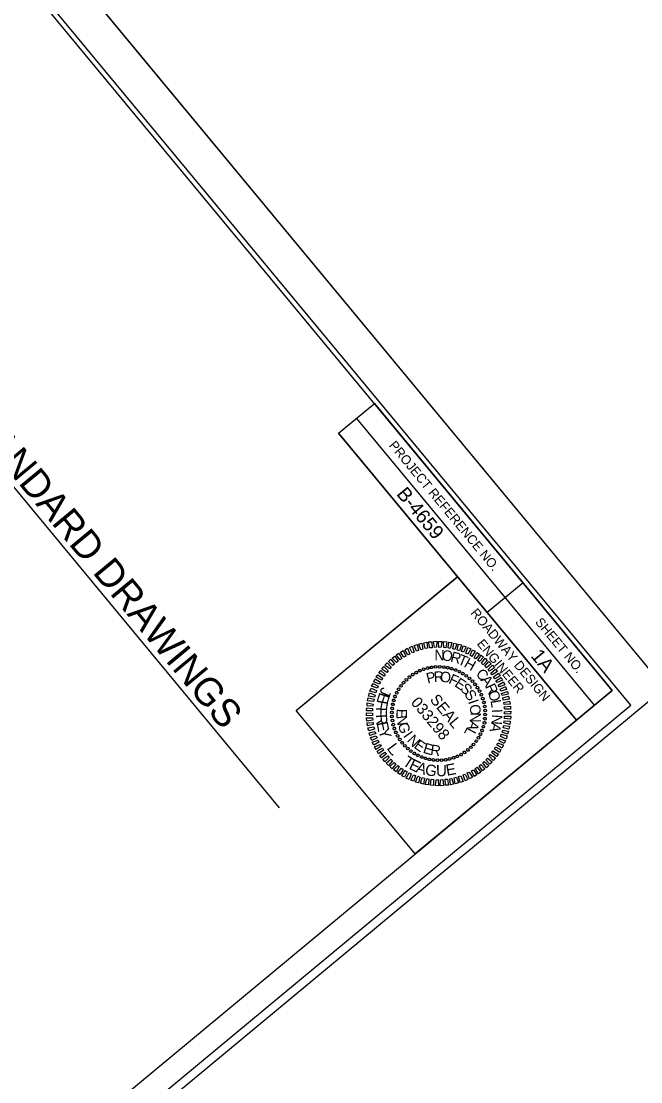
# Model space of a CAD drawing. Extents: x 2054826 to 2060231, y 685508 to 690809.
# Drawn here: x 2056398 to 2056731, y 685996 to 686565 of the extents above; entities that cross this region are included whole.
import ezdxf

# ---------------------------------------------------------------- set-up
doc = ezdxf.new("R2010")
doc.units = 0
for name, color, linetype in [('Prop DSN Text', 7, 'Continuous'), ('Sheet Cutting Line CELL', 7, 'Continuous'), ('Sheet Data Field CELL', 7, 'Continuous'), ('Sheet Plan CELL', 7, 'Continuous'), ('Sheet Plot Border Inside CELL', 7, 'Continuous'), ('Sheet Plot Border Outside CELL', 7, 'Continuous'), ('Sheet Professional Seal CELL', 7, 'Continuous')]:
    doc.layers.add(name, color=color, linetype=linetype)

msp = doc.modelspace()

# ---------------------------------------------------------------- linework, layer by layer
at = {"layer": 'Prop DSN Text'}
msp.add_line((2056196.26, 686553.18), (2056536.33, 686143.09), dxfattribs=at)
at = {"layer": 'Sheet Cutting Line CELL'}
msp.add_line((2056743.36, 686207.34), (2055668.74, 687503.24), dxfattribs=at)
at = {"layer": 'Sheet Plan CELL'}
for p, q in [((2056577.83, 686352.04), (2056705.53, 686198.05)), ((2056568.21, 686344.06), (2056695.91, 686190.07)), ((2056568.21, 686344.06), (2056695.91, 686190.07)), ((2056632.08, 686267.05), (2056545.52, 686195.27)), ((2056667.28, 686263.76), (2056648.03, 686247.81))]:
    msp.add_line(p, q, dxfattribs=at)
for points in [[(2056715.19, 686206.06), (2055757.7, 687360.71), (2054949.45, 686690.47), (2055906.94, 685535.82)], [(2056587.49, 686360.05), (2056715.19, 686206.06), (2056695.91, 686190.07), (2056568.21, 686344.06)], [(2056632.08, 686267.05), (2056695.91, 686190.07), (2056609.31, 686118.26), (2056545.48, 686195.24)]]:
    msp.add_lwpolyline(points, close=True, dxfattribs=at)
at = {"layer": 'Sheet Plot Border Inside CELL'}
msp.add_lwpolyline([(2054849.54, 686807.03), (2055912.99, 685524.6), (2056725.1, 686198.04), (2055661.64, 687480.47)], close=True, dxfattribs=at)
at = {"layer": 'Sheet Plot Border Outside CELL'}
msp.add_lwpolyline([(2054825.85, 686804.27), (2055900.47, 685508.37), (2056743.36, 686207.34), (2055668.74, 687503.24)], close=True, dxfattribs=at)
at = {"layer": 'Sheet Professional Seal CELL'}
for p, q in [((2056622.51, 686218.76), (2056622.51, 686218.76)), ((2056606.23, 686213.25), (2056606.23, 686213.25)), ((2056608.02, 686214.54), (2056608.02, 686214.54)), ((2056609.9, 686215.64), (2056609.9, 686215.64)), ((2056611.8, 686216.63), (2056611.8, 686216.63)), ((2056613.86, 686217.44), (2056613.86, 686217.44)), ((2056615.98, 686218.02), (2056615.98, 686218.02)), ((2056618.12, 686218.49), (2056618.12, 686218.49)), ((2056620.3, 686218.68), (2056620.3, 686218.68)), ((2056624.66, 686218.59), (2056624.66, 686218.59)), ((2056626.87, 686218.28), (2056626.87, 686218.28)), ((2056628.95, 686217.73), (2056628.95, 686217.73)), ((2056631.05, 686217), (2056631.05, 686217)), ((2056633.06, 686216.14), (2056633.06, 686216.14)), ((2056634.95, 686215.11), (2056634.95, 686215.11)), ((2056636.76, 686213.88), (2056636.76, 686213.88)), ((2056601.67, 686208.49), (2056601.67, 686208.49)), ((2056603.1, 686210.2), (2056603.1, 686210.2)), ((2056604.57, 686211.8), (2056604.57, 686211.8)), ((2056638.47, 686212.44), (2056638.47, 686212.44)), ((2056640.07, 686210.98), (2056640.07, 686210.98)), ((2056641.51, 686209.31), (2056641.51, 686209.31)), ((2056642.8, 686207.53), (2056642.8, 686207.53)), ((2056598.54, 686202.78), (2056598.54, 686202.78)), ((2056599.4, 686204.79), (2056599.4, 686204.79)), ((2056600.43, 686206.69), (2056600.43, 686206.69)), ((2056643.91, 686205.65), (2056643.91, 686205.65)), ((2056644.9, 686203.74), (2056644.9, 686203.74)), ((2056645.7, 686201.68), (2056645.7, 686201.68)), ((2056596.95, 686196.39), (2056596.95, 686196.39)), ((2056597.26, 686198.6), (2056597.26, 686198.6)), ((2056597.81, 686200.68), (2056597.81, 686200.68)), ((2056646.29, 686199.57), (2056646.29, 686199.57)), ((2056646.76, 686197.43), (2056646.76, 686197.43)), ((2056596.79, 686194.24), (2056596.79, 686194.24)), ((2056596.86, 686192.04), (2056596.86, 686192.04)), ((2056621.91, 686193.64), (2056621.91, 686193.64)), ((2056646.86, 686190.88), (2056646.86, 686190.88)), ((2056646.95, 686195.24), (2056646.95, 686195.24)), ((2056647.03, 686193.03), (2056647.03, 686193.03)), ((2056597.05, 686189.85), (2056597.05, 686189.85)), ((2056597.53, 686187.71), (2056597.53, 686187.71)), ((2056598.11, 686185.6), (2056598.11, 686185.6)), ((2056646, 686186.6), (2056646, 686186.6)), ((2056646.55, 686188.68), (2056646.55, 686188.68)), ((2056598.91, 686183.53), (2056598.91, 686183.53)), ((2056599.91, 686181.63), (2056599.91, 686181.63)), ((2056601.01, 686179.75), (2056601.01, 686179.75)), ((2056643.38, 686180.59), (2056643.38, 686180.59)), ((2056644.41, 686182.48), (2056644.41, 686182.48)), ((2056645.27, 686184.5), (2056645.27, 686184.5)), ((2056602.3, 686177.96), (2056602.3, 686177.96)), ((2056603.74, 686176.3), (2056603.74, 686176.3)), ((2056605.34, 686174.84), (2056605.34, 686174.84)), ((2056607.06, 686173.4), (2056607.06, 686173.4)), ((2056637.58, 686174.03), (2056637.58, 686174.03)), ((2056639.24, 686175.47), (2056639.24, 686175.47)), ((2056640.71, 686177.08), (2056640.71, 686177.08)), ((2056642.14, 686178.79), (2056642.14, 686178.79)), ((2056608.86, 686172.17), (2056608.86, 686172.17)), ((2056610.75, 686171.14), (2056610.75, 686171.14)), ((2056612.76, 686170.28), (2056612.76, 686170.28)), ((2056614.86, 686169.55), (2056614.86, 686169.55)), ((2056616.94, 686169), (2056616.94, 686169)), ((2056619.15, 686168.68), (2056619.15, 686168.68)), ((2056621.3, 686168.52), (2056621.3, 686168.52)), ((2056623.51, 686168.6), (2056623.51, 686168.6)), ((2056625.69, 686168.78), (2056625.69, 686168.78)), ((2056627.83, 686169.26), (2056627.83, 686169.26)), ((2056629.95, 686169.84), (2056629.95, 686169.84)), ((2056632.01, 686170.64), (2056632.01, 686170.64)), ((2056633.91, 686171.64), (2056633.91, 686171.64)), ((2056635.79, 686172.74), (2056635.79, 686172.74))]:
    msp.add_line(p, q, dxfattribs=at)
for points in [[(2056610.02, 686227.17), (2056608.73, 686230.13), (2056610.34, 686230.62), (2056611.17, 686227.42)], [(2056612.35, 686227.8), (2056611.25, 686230.92), (2056612.93, 686231.34), (2056613.51, 686228.12)], [(2056614.76, 686228.5), (2056613.9, 686231.49), (2056615.57, 686231.91), (2056615.87, 686228.65)], [(2056617.18, 686228.95), (2056616.54, 686232.06), (2056618.26, 686232.19), (2056618.38, 686228.91)], [(2056619.67, 686229.07), (2056619.26, 686232.24), (2056620.98, 686232.43), (2056620.82, 686229.18)], [(2056622.09, 686229.13), (2056621.94, 686232.38), (2056623.64, 686232.36), (2056623.23, 686229.17)], [(2056624.67, 686229), (2056624.62, 686232.27), (2056626.31, 686232.04), (2056625.8, 686228.89)], [(2056627.07, 686228.84), (2056627.36, 686231.94), (2056629.05, 686231.78), (2056628.22, 686228.56)], [(2056629.54, 686228.29), (2056630.02, 686231.48), (2056631.69, 686231.11), (2056630.65, 686227.98)], [(2056631.91, 686227.79), (2056632.69, 686230.84), (2056634.25, 686230.45), (2056633.08, 686227.32)], [(2056599.25, 686220.97), (2056597.05, 686223.37), (2056598.36, 686224.46), (2056600.17, 686221.73)], [(2056601.2, 686222.52), (2056599.2, 686225.09), (2056600.54, 686226.06), (2056602.19, 686223.21)], [(2056603.21, 686223.86), (2056601.4, 686226.52), (2056602.83, 686227.45), (2056604.29, 686224.44)], [(2056605.43, 686225.18), (2056603.76, 686227.82), (2056605.29, 686228.64), (2056606.49, 686225.54)], [(2056607.69, 686226.21), (2056606.21, 686229.02), (2056607.7, 686229.8), (2056608.75, 686226.58)], [(2056634.28, 686226.89), (2056635.17, 686230.04), (2056636.78, 686229.36), (2056635.35, 686226.54)], [(2056636.57, 686226), (2056637.71, 686229.02), (2056639.24, 686228.28), (2056637.62, 686225.44)], [(2056638.79, 686224.98), (2056640.19, 686227.83), (2056641.61, 686227.06), (2056639.82, 686224.21)], [(2056640.97, 686223.61), (2056642.54, 686226.41), (2056643.88, 686225.5), (2056641.91, 686223.02)], [(2056643, 686222.17), (2056644.75, 686224.99), (2056646.11, 686223.91), (2056643.86, 686221.52)], [(2056594.14, 686215.69), (2056591.39, 686217.51), (2056592.51, 686218.82), (2056594.75, 686216.59)], [(2056595.7, 686217.57), (2056593.08, 686219.62), (2056594.3, 686220.82), (2056596.49, 686218.49)], [(2056597.35, 686219.33), (2056594.97, 686221.58), (2056596.21, 686222.74), (2056598.21, 686220.17)], [(2056644.95, 686220.68), (2056646.91, 686223.33), (2056648.07, 686222.16), (2056645.84, 686219.85)], [(2056646.72, 686219.02), (2056648.83, 686221.49), (2056650.07, 686220.31), (2056647.6, 686218.19)], [(2056648.5, 686217.26), (2056650.85, 686219.52), (2056651.86, 686218.22), (2056649.23, 686216.3)], [(2056591.34, 686211.55), (2056588.39, 686213.07), (2056589.23, 686214.48), (2056591.82, 686212.6)], [(2056592.67, 686213.7), (2056589.74, 686215.43), (2056590.82, 686216.71), (2056593.26, 686214.64)], [(2056650, 686215.38), (2056652.5, 686217.45), (2056653.51, 686216.15), (2056650.73, 686214.42)], [(2056651.48, 686213.36), (2056654.11, 686215.28), (2056654.93, 686213.81), (2056652.09, 686212.3)], [(2056589.08, 686207.21), (2056585.95, 686208.25), (2056586.73, 686209.74), (2056589.43, 686208.28)], [(2056590.1, 686209.36), (2056587.06, 686210.67), (2056587.88, 686212.19), (2056590.63, 686210.44)], [(2056652.7, 686211.25), (2056655.45, 686212.95), (2056656.31, 686211.52), (2056653.35, 686210.23)], [(2056653.91, 686208.94), (2056656.73, 686210.63), (2056657.51, 686209.06), (2056654.38, 686207.97)], [(2056654.94, 686206.68), (2056657.8, 686208.08), (2056658.41, 686206.57), (2056655.34, 686205.65)], [(2056586.93, 686200.1), (2056583.73, 686200.43), (2056584.1, 686202.1), (2056587.25, 686201.28)], [(2056587.47, 686202.5), (2056584.29, 686203.04), (2056584.8, 686204.7), (2056587.82, 686203.57)], [(2056588.22, 686204.81), (2056585.07, 686205.64), (2056585.61, 686207.32), (2056588.54, 686205.99)], [(2056655.68, 686204.37), (2056658.84, 686205.5), (2056659.27, 686204.04), (2056656.15, 686203.26)], [(2056656.39, 686202.03), (2056659.46, 686202.95), (2056659.91, 686201.31), (2056656.67, 686200.83)], [(2056586.46, 686195.1), (2056583.15, 686195.02), (2056583.31, 686196.71), (2056586.43, 686196.31)], [(2056586.66, 686197.6), (2056583.48, 686197.76), (2056583.64, 686199.45), (2056586.8, 686198.69)], [(2056656.97, 686199.53), (2056660.03, 686200.31), (2056660.33, 686198.61), (2056657.11, 686198.41)], [(2056657.18, 686197.16), (2056660.53, 686197.67), (2056660.55, 686196), (2056657.42, 686195.93)], [(2056586.48, 686192.65), (2056583.18, 686192.32), (2056583.2, 686194.02), (2056586.41, 686193.83)], [(2056586.64, 686190.11), (2056583.29, 686189.61), (2056583.26, 686191.28), (2056586.4, 686191.34)], [(2056657.33, 686194.63), (2056660.63, 686194.96), (2056660.61, 686193.26), (2056657.4, 686193.45)], [(2056657.35, 686192.18), (2056660.66, 686192.26), (2056660.5, 686190.57), (2056657.38, 686190.97)], [(2056586.84, 686187.75), (2056583.79, 686186.97), (2056583.48, 686188.67), (2056586.7, 686188.87)], [(2056587.42, 686185.25), (2056584.36, 686184.33), (2056583.9, 686185.97), (2056587.15, 686186.44)], [(2056656.34, 686184.78), (2056659.52, 686184.23), (2056659.01, 686182.58), (2056655.99, 686183.71)], [(2056656.88, 686187.18), (2056660.08, 686186.84), (2056659.71, 686185.17), (2056656.56, 686186)], [(2056657.15, 686189.67), (2056660.33, 686189.52), (2056660.17, 686187.83), (2056657.01, 686188.59)], [(2056588.13, 686182.91), (2056584.97, 686181.78), (2056584.54, 686183.24), (2056587.66, 686184.02)], [(2056588.87, 686180.6), (2056586.01, 686179.2), (2056585.4, 686180.71), (2056588.47, 686181.63)], [(2056589.9, 686178.34), (2056587.08, 686176.65), (2056586.31, 686178.21), (2056589.43, 686179.31)], [(2056654.73, 686180.06), (2056657.86, 686179.03), (2056657.08, 686177.54), (2056654.38, 686179)], [(2056655.59, 686182.47), (2056658.75, 686181.64), (2056658.2, 686179.95), (2056655.27, 686181.29)], [(2056591.11, 686176.03), (2056588.36, 686174.33), (2056587.5, 686175.76), (2056590.46, 686177.04)], [(2056592.33, 686173.92), (2056589.7, 686172), (2056588.88, 686173.46), (2056591.72, 686174.97)], [(2056651.14, 686173.58), (2056654.07, 686171.85), (2056652.99, 686170.57), (2056650.55, 686172.64)], [(2056652.48, 686175.73), (2056655.42, 686174.21), (2056654.58, 686172.8), (2056651.99, 686174.67)], [(2056653.71, 686177.92), (2056656.75, 686176.61), (2056655.93, 686175.09), (2056653.18, 686176.84)], [(2056593.81, 686171.9), (2056591.31, 686169.83), (2056590.3, 686171.13), (2056593.09, 686172.86)], [(2056595.31, 686170.02), (2056592.96, 686167.76), (2056591.95, 686169.06), (2056594.58, 686170.98)], [(2056597.09, 686168.26), (2056594.98, 686165.79), (2056593.74, 686166.97), (2056596.21, 686169.09)], [(2056646.46, 686167.95), (2056648.84, 686165.7), (2056647.6, 686164.54), (2056645.6, 686167.1)], [(2056648.11, 686169.71), (2056650.73, 686167.65), (2056649.52, 686166.45), (2056647.32, 686168.79)], [(2056649.67, 686171.59), (2056652.42, 686169.77), (2056651.3, 686168.45), (2056649.06, 686170.69)], [(2056598.86, 686166.6), (2056596.91, 686163.94), (2056595.74, 686165.12), (2056597.98, 686167.43)], [(2056600.81, 686165.11), (2056599.06, 686162.29), (2056597.7, 686163.37), (2056599.95, 686165.75)], [(2056602.85, 686163.67), (2056601.27, 686160.87), (2056599.93, 686161.78), (2056601.91, 686164.26)], [(2056605.03, 686162.3), (2056603.62, 686159.45), (2056602.2, 686160.22), (2056604, 686163.07)], [(2056607.24, 686161.27), (2056606.1, 686158.26), (2056604.58, 686159), (2056606.19, 686161.83)], [(2056638.38, 686162.1), (2056640.06, 686159.45), (2056638.52, 686158.64), (2056637.32, 686161.73)], [(2056640.6, 686163.42), (2056642.41, 686160.76), (2056640.98, 686159.83), (2056639.52, 686162.84)], [(2056642.61, 686164.76), (2056644.61, 686162.19), (2056643.27, 686161.21), (2056641.62, 686164.07)], [(2056644.57, 686166.31), (2056646.76, 686163.91), (2056645.45, 686162.82), (2056643.64, 686165.55)], [(2056609.53, 686160.39), (2056608.64, 686157.24), (2056607.03, 686157.92), (2056608.47, 686160.73)], [(2056611.9, 686159.49), (2056611.12, 686156.44), (2056609.56, 686156.83), (2056610.74, 686159.95)], [(2056614.27, 686158.99), (2056613.79, 686155.8), (2056612.12, 686156.17), (2056613.16, 686159.3)], [(2056616.74, 686158.44), (2056616.45, 686155.34), (2056614.76, 686155.49), (2056615.59, 686158.72)], [(2056619.14, 686158.28), (2056619.19, 686155.01), (2056617.5, 686155.24), (2056618.01, 686158.39)], [(2056621.72, 686158.15), (2056621.88, 686154.9), (2056620.17, 686154.92), (2056620.58, 686158.11)], [(2056624.14, 686158.21), (2056624.55, 686155.04), (2056622.83, 686154.85), (2056622.99, 686158.1)], [(2056626.63, 686158.33), (2056627.27, 686155.22), (2056625.55, 686155.09), (2056625.43, 686158.37)], [(2056629.06, 686158.78), (2056629.91, 686155.78), (2056628.24, 686155.37), (2056627.94, 686158.63)], [(2056631.46, 686159.47), (2056632.56, 686156.35), (2056630.89, 686155.94), (2056630.3, 686159.16)], [(2056633.8, 686160.11), (2056635.08, 686157.15), (2056633.47, 686156.66), (2056632.64, 686159.86)], [(2056636.12, 686161.06), (2056637.6, 686158.26), (2056636.11, 686157.48), (2056635.06, 686160.7)]]:
    msp.add_lwpolyline(points, close=True, dxfattribs=at)
for centre, major_axis in [((2056615.98, 686218.01), (-0.17, 0.7)), ((2056618.13, 686218.43), (-0.109, 0.712)), ((2056620.3, 686218.67), (-0.046, 0.719)), ((2056622.49, 686218.71), (0.017, 0.72)), ((2056624.67, 686218.57), (0.079, 0.716)), ((2056626.83, 686218.23), (0.141, 0.706)), ((2056606.24, 686213.22), (-0.45, 0.562)), ((2056608, 686214.51), (-0.399, 0.599)), ((2056609.87, 686215.64), (-0.345, 0.632)), ((2056611.84, 686216.61), (-0.289, 0.659)), ((2056613.88, 686217.4), (-0.23, 0.682)), ((2056628.96, 686217.71), (0.202, 0.691)), ((2056631.03, 686217), (0.262, 0.671)), ((2056633.03, 686216.12), (0.319, 0.645)), ((2056634.95, 686215.06), (0.374, 0.615)), ((2056636.76, 686213.84), (0.427, 0.58)), ((2056638.47, 686212.47), (0.476, 0.541)), ((2056600.48, 686206.68), (-0.615, 0.374)), ((2056601.7, 686208.5), (-0.58, 0.427)), ((2056603.07, 686210.2), (-0.541, 0.476)), ((2056604.59, 686211.78), (-0.497, 0.521)), ((2056640.05, 686210.96), (0.521, 0.497)), ((2056641.49, 686209.31), (0.562, 0.45)), ((2056642.78, 686207.54), (0.599, 0.399)), ((2056598.54, 686202.76), (-0.671, 0.262)), ((2056599.43, 686204.76), (-0.645, 0.319)), ((2056643.91, 686205.67), (0.632, 0.345)), ((2056644.88, 686203.71), (0.659, 0.289)), ((2056645.67, 686201.67), (0.682, 0.23)), ((2056596.98, 686196.41), (-0.716, 0.079)), ((2056597.31, 686198.57), (-0.706, 0.141)), ((2056597.84, 686200.69), (-0.691, 0.202)), ((2056646.28, 686199.57), (0.7, 0.17)), ((2056646.7, 686197.42), (0.712, 0.109)), ((2056646.93, 686195.24), (0.719, 0.046)), ((2056596.83, 686194.22), (-0.72, 0.017)), ((2056596.88, 686192.04), (-0.719, -0.046)), ((2056597.11, 686189.86), (-0.712, -0.109)), ((2056646.83, 686190.87), (0.716, -0.079)), ((2056646.98, 686193.06), (0.72, -0.017)), ((2056597.54, 686187.71), (-0.7, -0.17)), ((2056598.15, 686185.61), (-0.682, -0.23)), ((2056645.27, 686184.52), (0.671, -0.262)), ((2056645.97, 686186.59), (0.691, -0.202)), ((2056646.5, 686188.71), (0.706, -0.141)), ((2056598.94, 686183.57), (-0.659, -0.289)), ((2056599.9, 686181.61), (-0.632, -0.345)), ((2056601.03, 686179.74), (-0.599, -0.399)), ((2056642.11, 686178.78), (0.58, -0.427)), ((2056643.33, 686180.6), (0.615, -0.374)), ((2056644.38, 686182.51), (0.645, -0.319)), ((2056602.32, 686177.97), (-0.562, -0.45)), ((2056603.76, 686176.32), (-0.521, -0.497)), ((2056605.34, 686174.81), (-0.476, -0.541)), ((2056607.05, 686173.43), (-0.427, -0.58)), ((2056635.81, 686172.77), (0.399, -0.599)), ((2056637.58, 686174.06), (0.45, -0.562)), ((2056639.22, 686175.5), (0.497, -0.521)), ((2056640.74, 686177.08), (0.541, -0.476)), ((2056608.86, 686172.22), (-0.374, -0.615)), ((2056610.78, 686171.16), (-0.319, -0.645)), ((2056612.78, 686170.28), (-0.262, -0.671)), ((2056614.85, 686169.57), (-0.202, -0.691)), ((2056616.98, 686169.05), (-0.141, -0.706)), ((2056619.14, 686168.71), (-0.079, -0.716)), ((2056621.32, 686168.57), (-0.017, -0.72)), ((2056623.51, 686168.61), (0.046, -0.719)), ((2056625.69, 686168.85), (0.109, -0.712)), ((2056627.83, 686169.27), (0.17, -0.7)), ((2056629.93, 686169.88), (0.23, -0.682)), ((2056631.97, 686170.67), (0.289, -0.659)), ((2056633.94, 686171.63), (0.345, -0.632))]:
    msp.add_ellipse(centre, major_axis=major_axis, ratio=0.999708, dxfattribs=at)

# ---------------------------------------------------------------- texts
at = {"layer": 'Prop DSN Text'}
msp.add_text('2012 ROADWAY ENGLISH STANDARD DRAWINGS', height=15, rotation=309.6672, dxfattribs=at).set_placement((2056200.16, 686553.28))
at = {"layer": 'Sheet Data Field CELL'}
for s, p in [('B-4659', (2056598.95, 686311.3)), ('1A', (2056671.07, 686224.41))]:
    msp.add_text(s, height=7.5, rotation=309.6672, dxfattribs=at).set_placement(p)
at = {"layer": 'Sheet Plan CELL'}
for s, height, p in [('PROJECT REFERENCE NO.', 5.0001, (2056594.97, 686337.41)), ('ROADWAY DESIGN', 5.0001, (2056638.84, 686247.46)), ('SHEET NO.', 5, (2056673.5, 686242.55)), ('ENGINEER', 5, (2056642.2, 686230.95))]:
    msp.add_text(s, height=height, rotation=309.6672, dxfattribs=at).set_placement(p)
at = {"layer": 'Sheet Professional Seal CELL'}
for s, height, rotation, p in [('N', 5.64, 359.0907, (2056619.64, 686222.22)), ('O', 5.64, 351.8889, (2056623.34, 686222.3)), ('R', 5.64, 344.6877, (2056627.93, 686221.63)), ('T', 5.64, 337.487, (2056631.79, 686220.41)), ('H', 5.64, 330.2867, (2056635.14, 686218.96)), ('P', 5.64, 13.0661, (2056616.02, 686209.67)), ('R', 5.64, 3.7069, (2056619.5, 686210.48)), ('O', 5.64, 354.3484, (2056622.5, 686210.7)), ('F', 5.64, 335.6342, (2056626.88, 686210.04)), ('C', 5.64, 315.8871, (2056641.53, 686214.39)), ('A', 5.64, 308.6875, (2056644.28, 686211.54)), ('J', 6, 247.2287, (2056591.43, 686208.11)), ('E', 5.64, 326.2783, (2056630.08, 686208.54)), ('S', 5.64, 316.9228, (2056633.09, 686206.55)), ('R', 5.64, 294.2883, (2056646.81, 686208.18)), ('E', 6, 252.4865, (2056590.23, 686205.26)), ('033298', 5.998, 309.6672, (2056606.71, 686199.42)), ('SEAL', 5.998, 309.6672, (2056616.94, 686200.95)), ('S', 5.64, 307.5676, (2056635.43, 686203.81)), ('O', 5.64, 287.0884, (2056648.37, 686205.12)), ('F', 6, 266.6124, (2056588.36, 686197.17)), ('F', 6, 259.5958, (2056589.04, 686201.25)), ('I', 5.64, 288.8568, (2056637.63, 686200.05)), ('O', 5.64, 279.5007, (2056638.37, 686198.07)), ('L', 5.64, 279.8881, (2056649.75, 686200.56)), ('R', 6, 273.629, (2056588.17, 686193.05)), ('E', 5.64, 267.9441, (2056599.39, 686196.27)), ('N', 5.64, 277.3012, (2056599.23, 686192.24)), ('A', 5.64, 251.4275, (2056638.79, 686190.36)), ('N', 5.64, 270.1438, (2056638.97, 686194.21)), ('N', 5.64, 265.4861, (2056650.67, 686193.26)), ('I', 5.64, 272.6873, (2056650.49, 686195.91)), ('E', 6, 281.1093, (2056588.54, 686188.66)), ('Y', 6, 288.2186, (2056589.41, 686184.57)), ('G', 5.64, 286.6574, (2056599.92, 686187.88)), ('L', 5.64, 242.0681, (2056637.37, 686186.66)), ('A', 5.64, 258.2844, (2056650.28, 686189.11)), ('I', 5.64, 305.3684, (2056602.64, 686181.62)), ('N', 5.64, 314.7236, (2056604.66, 686178.95)), ('E', 5.64, 324.079, (2056608.28, 686175.52)), ('L', 6, 306.332, (2056593.84, 686174.92)), ('E', 5.64, 342.7913, (2056613.17, 686172.69)), ('R', 5.64, 352.1486, (2056617.24, 686171.46)), ('.', 6, 312.6068, (2056596.05, 686171.96)), ('T', 6, 326.8409, (2056602.18, 686166.27)), ('E', 6, 333.6411, (2056605.56, 686164.13)), ('A', 6, 340.7505, (2056609.34, 686162.33)), ('G', 6, 349.5908, (2056614.3, 686160.77)), ('U', 6, 0.3166, (2056620.55, 686159.93)), ('E', 6, 10.2542, (2056626.38, 686160.2))]:
    msp.add_text(s, height=height, rotation=rotation, dxfattribs=at).set_placement(p)

doc.saveas('drawing.dxf')
